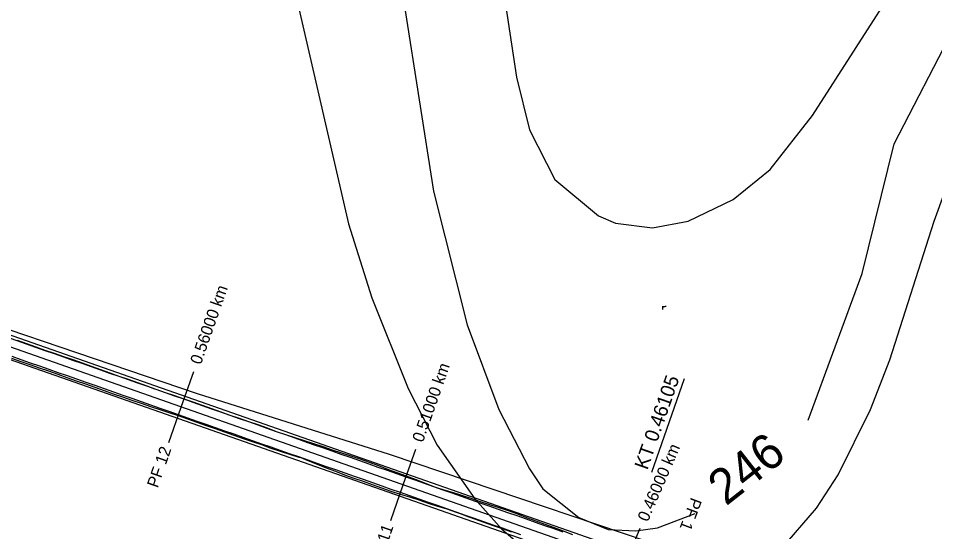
# Model space of a CAD drawing. Extents: x -555887 to -552101, y -1100251 to -1096546.
# Drawn here: x -553807.8 to -553613.1, y -1097242.2 to -1097133.2 of the extents above; entities that cross this region are included whole.
import ezdxf

# ---------------------------------------------------------------- set-up
doc = ezdxf.new("R2010")
doc.units = 0
for name, color, linetype in [('PARCELY_cesty', 7, 'Continuous'), ('POLYGONY_SITUACE_PF', 7, 'Continuous'), ('POLYGONY_SITUACE_PF_POPISY', 7, 'Continuous'), ('POLYGONY_SITUACE_PO', 7, 'Continuous'), ('vrstevnice', 7, 'Continuous'), ('ZSST', 7, 'Continuous')]:
    doc.layers.add(name, color=color, linetype=linetype)

msp = doc.modelspace()

# ---------------------------------------------------------------- linework, layer by layer
msp.add_line((-553673.2, -1097229.57), (-553666.23, -1097209.67))
at = {"layer": 'PARCELY_cesty'}
for points in [[(-553929.46, -1097158.38), (-553673.4, -1097248.15), (-553668.21, -1097254.17), (-553665.73, -1097263.94)], [(-553931.98, -1097162.8), (-553680.76, -1097250.77), (-553678.23, -1097251.97), (-553676.12, -1097253.6), (-553674.4, -1097255.65), (-553673.16, -1097258.01), (-553672.44, -1097260.58), (-553672.29, -1097263.25), (-553672.86, -1097266.82)]]:
    msp.add_lwpolyline(points, dxfattribs=at)
at = {"layer": 'POLYGONY_SITUACE_PF'}
for p, q in [((-553773.19, -1097215.75), (-553770.55, -1097208.2)), ((-553775.84, -1097223.3), (-553773.19, -1097215.75)), ((-553726, -1097232.27), (-553723.36, -1097224.72)), ((-553728.65, -1097239.82), (-553726, -1097232.27)), ((-553678.82, -1097248.83), (-553675.66, -1097241.49))]:
    msp.add_line(p, q, dxfattribs=at)
at = {"layer": 'POLYGONY_SITUACE_PO'}
for p, q in [((-553679.81, -1097248.45), (-553930.54, -1097160.65)), ((-553804.07, -1097203.08), (-553928.82, -1097159.4)), ((-553806.04, -1097202.39), (-553808.01, -1097201.7)), ((-553806.01, -1097202.3), (-553807.97, -1097201.6)), ((-553804.07, -1097203.08), (-553806.04, -1097202.39)), ((-553804.05, -1097203), (-553806.01, -1097202.3)), ((-553802.11, -1097203.77), (-553804.07, -1097203.08)), ((-553802.11, -1097203.77), (-553804.07, -1097203.08)), ((-553802.08, -1097203.7), (-553804.05, -1097203)), ((-553800.14, -1097204.46), (-553802.11, -1097203.77)), ((-553800.14, -1097204.46), (-553802.11, -1097203.77)), ((-553800.12, -1097204.4), (-553802.08, -1097203.7)), ((-553809.29, -1097205.38), (-553807.32, -1097206.05)), ((-553807.2, -1097205.7), (-553809.16, -1097205.01)), ((-553807.2, -1097205.7), (-553809.16, -1097205.01)), ((-553807.32, -1097206.05), (-553805.35, -1097206.72)), ((-553805.23, -1097206.39), (-553807.2, -1097205.7)), ((-553805.23, -1097206.39), (-553807.2, -1097205.7)), ((-553798.18, -1097205.15), (-553800.14, -1097204.46)), ((-553798.18, -1097205.15), (-553800.14, -1097204.46)), ((-553798.14, -1097205.05), (-553800.12, -1097204.4)), ((-553796.21, -1097205.84), (-553798.18, -1097205.15)), ((-553796.21, -1097205.84), (-553798.18, -1097205.15)), ((-553796.17, -1097205.72), (-553798.14, -1097205.05)), ((-553794.24, -1097206.52), (-553796.21, -1097205.84)), ((-553794.24, -1097206.52), (-553796.21, -1097205.84)), ((-553794.21, -1097206.43), (-553796.17, -1097205.72)), ((-553805.35, -1097206.72), (-553803.38, -1097207.39)), ((-553803.27, -1097207.07), (-553805.23, -1097206.39)), ((-553803.27, -1097207.07), (-553805.23, -1097206.39)), ((-553803.38, -1097207.39), (-553801.41, -1097208.07)), ((-553801.3, -1097207.76), (-553803.27, -1097207.07)), ((-553801.3, -1097207.76), (-553803.27, -1097207.07)), ((-553799.33, -1097208.45), (-553801.3, -1097207.76)), ((-553799.33, -1097208.45), (-553801.3, -1097207.76)), ((-553792.28, -1097207.21), (-553794.24, -1097206.52)), ((-553792.28, -1097207.21), (-553794.24, -1097206.52)), ((-553792.25, -1097207.14), (-553794.21, -1097206.43)), ((-553790.31, -1097207.9), (-553792.28, -1097207.21)), ((-553790.31, -1097207.9), (-553792.28, -1097207.21)), ((-553790.3, -1097207.86), (-553792.25, -1097207.14)), ((-553788.34, -1097208.59), (-553790.31, -1097207.9)), ((-553788.34, -1097208.59), (-553790.31, -1097207.9)), ((-553788.33, -1097208.56), (-553790.3, -1097207.86)), ((-553801.41, -1097208.07), (-553799.45, -1097208.78)), ((-553799.45, -1097208.78), (-553797.49, -1097209.49)), ((-553797.37, -1097209.14), (-553799.33, -1097208.45)), ((-553797.37, -1097209.14), (-553799.33, -1097208.45)), ((-553797.49, -1097209.49), (-553795.51, -1097210.16)), ((-553795.4, -1097209.83), (-553797.37, -1097209.14)), ((-553795.4, -1097209.83), (-553797.37, -1097209.14)), ((-553793.43, -1097210.52), (-553795.4, -1097209.83)), ((-553793.43, -1097210.52), (-553795.4, -1097209.83)), ((-553786.38, -1097209.28), (-553788.34, -1097208.59)), ((-553786.38, -1097209.28), (-553788.34, -1097208.59)), ((-553786.37, -1097209.25), (-553788.33, -1097208.56)), ((-553784.41, -1097209.97), (-553786.38, -1097209.28)), ((-553784.41, -1097209.97), (-553786.38, -1097209.28)), ((-553784.4, -1097209.92), (-553786.37, -1097209.25)), ((-553782.45, -1097210.66), (-553784.41, -1097209.97)), ((-553782.45, -1097210.66), (-553784.41, -1097209.97)), ((-553782.43, -1097210.62), (-553784.4, -1097209.92)), ((-553795.51, -1097210.16), (-553793.55, -1097210.84)), ((-553793.55, -1097210.84), (-553791.57, -1097211.5)), ((-553791.47, -1097211.2), (-553793.43, -1097210.52)), ((-553791.47, -1097211.2), (-553793.43, -1097210.52)), ((-553791.57, -1097211.5), (-553789.61, -1097212.22)), ((-553789.5, -1097211.89), (-553791.47, -1097211.2)), ((-553789.5, -1097211.89), (-553791.47, -1097211.2)), ((-553787.53, -1097212.58), (-553789.5, -1097211.89)), ((-553787.53, -1097212.58), (-553789.5, -1097211.89)), ((-553780.48, -1097211.34), (-553782.45, -1097210.66)), ((-553780.48, -1097211.34), (-553782.45, -1097210.66)), ((-553780.47, -1097211.32), (-553782.43, -1097210.62)), ((-553778.51, -1097212.03), (-553780.48, -1097211.34)), ((-553778.51, -1097212.03), (-553780.48, -1097211.34)), ((-553778.84, -1097211.92), (-553780.47, -1097211.32)), ((-553789.61, -1097212.22), (-553787.65, -1097212.91)), ((-553787.65, -1097212.91), (-553785.68, -1097213.6)), ((-553785.57, -1097213.27), (-553787.53, -1097212.58)), ((-553785.57, -1097213.27), (-553787.53, -1097212.58)), ((-553785.68, -1097213.6), (-553783.71, -1097214.27)), ((-553783.6, -1097213.96), (-553785.57, -1097213.27)), ((-553783.6, -1097213.96), (-553785.57, -1097213.27)), ((-553778.51, -1097212.03), (-553778.84, -1097211.92)), ((-553776.55, -1097212.72), (-553778.51, -1097212.03)), ((-553776.54, -1097212.69), (-553778.51, -1097212.03)), ((-553776.55, -1097212.72), (-553778.51, -1097212.03)), ((-553774.58, -1097213.41), (-553776.55, -1097212.72)), ((-553774.58, -1097213.41), (-553776.55, -1097212.72)), ((-553774.56, -1097213.36), (-553776.54, -1097212.69)), ((-553772.61, -1097214.1), (-553774.58, -1097213.41)), ((-553772.61, -1097214.1), (-553774.58, -1097213.41)), ((-553772.6, -1097214.04), (-553774.56, -1097213.36)), ((-553783.71, -1097214.27), (-553781.73, -1097214.92)), ((-553781.64, -1097214.65), (-553783.6, -1097213.96)), ((-553781.64, -1097214.65), (-553783.6, -1097213.96)), ((-553781.73, -1097214.92), (-553779.76, -1097215.6)), ((-553779.67, -1097215.34), (-553781.64, -1097214.65)), ((-553779.67, -1097215.34), (-553781.64, -1097214.65)), ((-553779.76, -1097215.6), (-553777.78, -1097216.25)), ((-553777.7, -1097216.02), (-553779.67, -1097215.34)), ((-553777.7, -1097216.02), (-553779.67, -1097215.34)), ((-553770.65, -1097214.79), (-553772.61, -1097214.1)), ((-553770.65, -1097214.79), (-553772.61, -1097214.1)), ((-553770.63, -1097214.72), (-553772.6, -1097214.04)), ((-553768.68, -1097215.48), (-553770.65, -1097214.79)), ((-553768.68, -1097215.48), (-553770.65, -1097214.79)), ((-553768.66, -1097215.42), (-553770.63, -1097214.72)), ((-553766.72, -1097216.16), (-553768.68, -1097215.48)), ((-553766.72, -1097216.16), (-553768.68, -1097215.48)), ((-553766.7, -1097216.13), (-553768.66, -1097215.42)), ((-553777.78, -1097216.25), (-553775.8, -1097216.89)), ((-553775.74, -1097216.71), (-553777.7, -1097216.02)), ((-553775.74, -1097216.71), (-553777.7, -1097216.02)), ((-553775.8, -1097216.89), (-553773.82, -1097217.54)), ((-553773.77, -1097217.4), (-553775.74, -1097216.71)), ((-553773.77, -1097217.4), (-553775.74, -1097216.71)), ((-553773.82, -1097217.54), (-553771.85, -1097218.22)), ((-553771.8, -1097218.09), (-553773.77, -1097217.4)), ((-553771.8, -1097218.09), (-553773.77, -1097217.4)), ((-553764.75, -1097216.85), (-553766.72, -1097216.16)), ((-553764.75, -1097216.85), (-553766.72, -1097216.16)), ((-553764.74, -1097216.83), (-553766.7, -1097216.13)), ((-553762.78, -1097217.54), (-553764.75, -1097216.85)), ((-553762.78, -1097217.54), (-553764.75, -1097216.85)), ((-553762.78, -1097217.52), (-553764.74, -1097216.83)), ((-553760.81, -1097218.2), (-553762.78, -1097217.52)), ((-553760.82, -1097218.23), (-553762.78, -1097217.54)), ((-553760.82, -1097218.23), (-553762.78, -1097217.54)), ((-553771.85, -1097218.22), (-553769.89, -1097218.93)), ((-553769.84, -1097218.78), (-553771.8, -1097218.09)), ((-553769.84, -1097218.78), (-553771.8, -1097218.09)), ((-553769.89, -1097218.93), (-553767.93, -1097219.64)), ((-553767.87, -1097219.47), (-553769.84, -1097218.78)), ((-553767.87, -1097219.47), (-553769.84, -1097218.78)), ((-553767.93, -1097219.64), (-553765.96, -1097220.32)), ((-553765.91, -1097220.16), (-553767.87, -1097219.47)), ((-553765.91, -1097220.16), (-553767.87, -1097219.47)), ((-553758.85, -1097218.92), (-553760.82, -1097218.23)), ((-553758.85, -1097218.92), (-553760.82, -1097218.23)), ((-553758.83, -1097218.86), (-553760.81, -1097218.2)), ((-553756.88, -1097219.61), (-553758.85, -1097218.92)), ((-553756.88, -1097219.61), (-553758.85, -1097218.92)), ((-553756.86, -1097219.53), (-553758.83, -1097218.86)), ((-553754.92, -1097220.29), (-553756.88, -1097219.61)), ((-553754.92, -1097220.29), (-553756.88, -1097219.61)), ((-553754.9, -1097220.25), (-553756.86, -1097219.53)), ((-553765.96, -1097220.32), (-553764, -1097221.01)), ((-553763.94, -1097220.84), (-553765.91, -1097220.16)), ((-553763.94, -1097220.84), (-553765.91, -1097220.16)), ((-553764, -1097221.01), (-553762.04, -1097221.72)), ((-553761.97, -1097221.53), (-553763.94, -1097220.84)), ((-553761.97, -1097221.53), (-553763.94, -1097220.84)), ((-553760.01, -1097222.22), (-553761.97, -1097221.53)), ((-553760.01, -1097222.22), (-553761.97, -1097221.53)), ((-553752.95, -1097220.98), (-553754.92, -1097220.29)), ((-553752.95, -1097220.98), (-553754.92, -1097220.29)), ((-553752.95, -1097220.98), (-553754.9, -1097220.25)), ((-553750.99, -1097221.67), (-553752.95, -1097220.98)), ((-553750.98, -1097221.66), (-553752.95, -1097220.98)), ((-553752.95, -1097220.98), (-553752.95, -1097220.98)), ((-553752.95, -1097220.98), (-553752.95, -1097220.98)), ((-553750.99, -1097221.67), (-553752.95, -1097220.98)), ((-553762.04, -1097221.72), (-553760.07, -1097222.4)), ((-553760.07, -1097222.4), (-553758.09, -1097223.05)), ((-553758.04, -1097222.91), (-553760.01, -1097222.22)), ((-553758.04, -1097222.91), (-553760.01, -1097222.22)), ((-553758.09, -1097223.05), (-553756.11, -1097223.7)), ((-553756.07, -1097223.6), (-553758.04, -1097222.91)), ((-553756.07, -1097223.6), (-553758.04, -1097222.91)), ((-553754.11, -1097224.29), (-553756.07, -1097223.6)), ((-553754.11, -1097224.29), (-553756.07, -1097223.6)), ((-553749.02, -1097222.36), (-553750.99, -1097221.67)), ((-553749.02, -1097222.36), (-553750.99, -1097221.67)), ((-553748.99, -1097222.29), (-553750.98, -1097221.66)), ((-553747.05, -1097223.05), (-553749.02, -1097222.36)), ((-553747.05, -1097223.05), (-553749.02, -1097222.36)), ((-553747.01, -1097222.93), (-553748.99, -1097222.29)), ((-553745.09, -1097223.74), (-553747.05, -1097223.05)), ((-553745.09, -1097223.74), (-553747.05, -1097223.05)), ((-553745.03, -1097223.57), (-553747.01, -1097222.93)), ((-553743.05, -1097224.22), (-553745.03, -1097223.57)), ((-553756.11, -1097223.7), (-553754.17, -1097224.45)), ((-553754.17, -1097224.45), (-553752.2, -1097225.15)), ((-553752.14, -1097224.98), (-553754.11, -1097224.29)), ((-553752.14, -1097224.98), (-553754.11, -1097224.29)), ((-553752.2, -1097225.15), (-553750.21, -1097225.77)), ((-553750.18, -1097225.66), (-553752.14, -1097224.98)), ((-553750.18, -1097225.66), (-553752.14, -1097224.98)), ((-553743.12, -1097224.43), (-553745.09, -1097223.74)), ((-553743.12, -1097224.43), (-553745.09, -1097223.74)), ((-553741.15, -1097225.11), (-553743.12, -1097224.43)), ((-553741.15, -1097225.11), (-553743.12, -1097224.43)), ((-553741.07, -1097224.87), (-553743.05, -1097224.22)), ((-553739.19, -1097225.8), (-553741.15, -1097225.11)), ((-553739.19, -1097225.8), (-553741.15, -1097225.11)), ((-553739.09, -1097225.52), (-553741.07, -1097224.87)), ((-553737.11, -1097226.19), (-553739.09, -1097225.52)), ((-553750.21, -1097225.77), (-553748.22, -1097226.37)), ((-553748.21, -1097226.35), (-553750.18, -1097225.66)), ((-553748.21, -1097226.35), (-553750.18, -1097225.66)), ((-553748.22, -1097226.37), (-553747.8, -1097226.49)), ((-553746.24, -1097227.04), (-553748.21, -1097226.35)), ((-553746.24, -1097227.04), (-553748.21, -1097226.35)), ((-553747.8, -1097226.49), (-553746.26, -1097227.1)), ((-553746.26, -1097227.1), (-553744.33, -1097227.87)), ((-553744.28, -1097227.73), (-553746.24, -1097227.04)), ((-553744.28, -1097227.73), (-553746.24, -1097227.04)), ((-553737.22, -1097226.49), (-553739.19, -1097225.8)), ((-553737.22, -1097226.49), (-553739.19, -1097225.8)), ((-553735.26, -1097227.18), (-553737.22, -1097226.49)), ((-553735.26, -1097227.18), (-553737.22, -1097226.49)), ((-553735.14, -1097226.85), (-553737.11, -1097226.19)), ((-553733.29, -1097227.87), (-553735.26, -1097227.18)), ((-553733.29, -1097227.87), (-553735.26, -1097227.18)), ((-553733.18, -1097227.54), (-553735.14, -1097226.85)), ((-553744.33, -1097227.87), (-553742.39, -1097228.63)), ((-553742.31, -1097228.42), (-553744.28, -1097227.73)), ((-553742.31, -1097228.42), (-553744.28, -1097227.73)), ((-553742.39, -1097228.63), (-553740.44, -1097229.37)), ((-553740.34, -1097229.11), (-553742.31, -1097228.42)), ((-553740.34, -1097229.11), (-553742.31, -1097228.42)), ((-553740.44, -1097229.37), (-553738.49, -1097230.12)), ((-553738.38, -1097229.79), (-553740.34, -1097229.11)), ((-553738.38, -1097229.79), (-553740.34, -1097229.11)), ((-553731.32, -1097228.56), (-553733.29, -1097227.87)), ((-553731.32, -1097228.56), (-553733.29, -1097227.87)), ((-553731.22, -1097228.26), (-553733.18, -1097227.54)), ((-553729.36, -1097229.25), (-553731.32, -1097228.56)), ((-553729.36, -1097229.25), (-553731.32, -1097228.56)), ((-553729.26, -1097228.98), (-553731.22, -1097228.26)), ((-553727.39, -1097229.93), (-553729.36, -1097229.25)), ((-553727.39, -1097229.93), (-553729.36, -1097229.25)), ((-553727.31, -1097229.7), (-553729.26, -1097228.98)), ((-553738.49, -1097230.12), (-553736.53, -1097230.82)), ((-553736.41, -1097230.48), (-553738.38, -1097229.79)), ((-553736.41, -1097230.48), (-553738.38, -1097229.79)), ((-553736.53, -1097230.82), (-553734.57, -1097231.52)), ((-553734.45, -1097231.17), (-553736.41, -1097230.48)), ((-553734.45, -1097231.17), (-553736.41, -1097230.48)), ((-553732.48, -1097231.86), (-553734.45, -1097231.17)), ((-553732.48, -1097231.86), (-553734.45, -1097231.17)), ((-553725.42, -1097230.62), (-553727.39, -1097229.93)), ((-553725.42, -1097230.62), (-553727.39, -1097229.93)), ((-553725.35, -1097230.42), (-553727.31, -1097229.7)), ((-553723.46, -1097231.31), (-553725.42, -1097230.62)), ((-553723.46, -1097231.31), (-553725.42, -1097230.62)), ((-553723.4, -1097231.16), (-553725.35, -1097230.42)), ((-553721.49, -1097232), (-553723.46, -1097231.31)), ((-553721.49, -1097232), (-553723.46, -1097231.31)), ((-553721.46, -1097231.9), (-553723.4, -1097231.16)), ((-553734.57, -1097231.52), (-553732.6, -1097232.21)), ((-553732.6, -1097232.21), (-553730.64, -1097232.9)), ((-553730.51, -1097232.55), (-553732.48, -1097231.86)), ((-553730.51, -1097232.55), (-553732.48, -1097231.86)), ((-553730.64, -1097232.9), (-553728.67, -1097233.58)), ((-553728.55, -1097233.24), (-553730.51, -1097232.55)), ((-553728.55, -1097233.24), (-553730.51, -1097232.55)), ((-553726.58, -1097233.93), (-553728.55, -1097233.24)), ((-553726.58, -1097233.93), (-553728.55, -1097233.24)), ((-553719.52, -1097232.69), (-553721.49, -1097232)), ((-553719.52, -1097232.69), (-553721.49, -1097232)), ((-553719.51, -1097232.66), (-553721.46, -1097231.9)), ((-553717.56, -1097233.38), (-553719.52, -1097232.69)), ((-553717.56, -1097233.38), (-553719.52, -1097232.69)), ((-553718.91, -1097232.9), (-553719.51, -1097232.66)), ((-553717.54, -1097233.31), (-553718.91, -1097232.9)), ((-553715.54, -1097233.91), (-553717.54, -1097233.31)), ((-553728.67, -1097233.58), (-553726.69, -1097234.23)), ((-553726.69, -1097234.23), (-553724.69, -1097234.84)), ((-553724.61, -1097234.61), (-553726.58, -1097233.93)), ((-553724.61, -1097234.61), (-553726.58, -1097233.93)), ((-553724.69, -1097234.84), (-553722.71, -1097235.48)), ((-553722.65, -1097235.3), (-553724.61, -1097234.61)), ((-553722.65, -1097235.3), (-553724.61, -1097234.61)), ((-553715.59, -1097234.07), (-553717.56, -1097233.38)), ((-553715.59, -1097234.07), (-553717.56, -1097233.38)), ((-553713.63, -1097234.75), (-553715.59, -1097234.07)), ((-553713.63, -1097234.75), (-553715.59, -1097234.07)), ((-553713.55, -1097234.54), (-553715.54, -1097233.91)), ((-553711.66, -1097235.44), (-553713.63, -1097234.75)), ((-553711.66, -1097235.44), (-553713.63, -1097234.75)), ((-553711.57, -1097235.18), (-553713.55, -1097234.54)), ((-553709.59, -1097235.85), (-553711.57, -1097235.18)), ((-553722.71, -1097235.48), (-553720.74, -1097236.14)), ((-553720.68, -1097235.99), (-553722.65, -1097235.3)), ((-553720.68, -1097235.99), (-553722.65, -1097235.3)), ((-553720.74, -1097236.14), (-553718.75, -1097236.78)), ((-553718.72, -1097236.68), (-553720.68, -1097235.99)), ((-553718.72, -1097236.68), (-553720.68, -1097235.99)), ((-553718.75, -1097236.78), (-553716.76, -1097237.4)), ((-553716.75, -1097237.37), (-553718.72, -1097236.68)), ((-553716.75, -1097237.37), (-553718.72, -1097236.68)), ((-553709.69, -1097236.13), (-553711.66, -1097235.44)), ((-553709.69, -1097236.13), (-553711.66, -1097235.44)), ((-553707.73, -1097236.82), (-553709.69, -1097236.13)), ((-553707.73, -1097236.82), (-553709.69, -1097236.13)), ((-553707.62, -1097236.51), (-553709.59, -1097235.85)), ((-553705.76, -1097237.51), (-553707.73, -1097236.82)), ((-553705.76, -1097237.51), (-553707.73, -1097236.82)), ((-553705.63, -1097237.14), (-553707.62, -1097236.51)), ((-553703.66, -1097237.82), (-553705.63, -1097237.14)), ((-553716.76, -1097237.4), (-553714.79, -1097238.09)), ((-553714.78, -1097238.06), (-553716.75, -1097237.37)), ((-553714.78, -1097238.06), (-553716.75, -1097237.37)), ((-553714.79, -1097238.09), (-553713.72, -1097238.43)), ((-553712.82, -1097238.75), (-553714.78, -1097238.06)), ((-553712.82, -1097238.75), (-553714.78, -1097238.06)), ((-553713.72, -1097238.43), (-553712.83, -1097238.77)), ((-553712.83, -1097238.77), (-553710.86, -1097239.47)), ((-553710.85, -1097239.43), (-553712.82, -1097238.75)), ((-553710.85, -1097239.43), (-553712.82, -1097238.75)), ((-553703.79, -1097238.2), (-553705.76, -1097237.51)), ((-553703.79, -1097238.2), (-553705.76, -1097237.51)), ((-553701.83, -1097238.88), (-553703.79, -1097238.2)), ((-553701.83, -1097238.88), (-553703.79, -1097238.2)), ((-553701.7, -1097238.53), (-553703.66, -1097237.82)), ((-553699.86, -1097239.57), (-553701.83, -1097238.88)), ((-553699.86, -1097239.57), (-553701.83, -1097238.88)), ((-553699.75, -1097239.25), (-553701.7, -1097238.53)), ((-553710.86, -1097239.47), (-553708.91, -1097240.2)), ((-553708.88, -1097240.12), (-553710.85, -1097239.43)), ((-553708.88, -1097240.12), (-553710.85, -1097239.43)), ((-553708.91, -1097240.2), (-553706.94, -1097240.89)), ((-553706.92, -1097240.81), (-553708.88, -1097240.12)), ((-553706.92, -1097240.81), (-553708.88, -1097240.12)), ((-553706.94, -1097240.89), (-553704.98, -1097241.57)), ((-553704.95, -1097241.5), (-553706.92, -1097240.81)), ((-553704.95, -1097241.5), (-553706.92, -1097240.81)), ((-553697.9, -1097240.26), (-553699.86, -1097239.57)), ((-553697.9, -1097240.26), (-553699.86, -1097239.57)), ((-553697.8, -1097239.98), (-553699.75, -1097239.25)), ((-553695.93, -1097240.95), (-553697.9, -1097240.26)), ((-553695.93, -1097240.95), (-553697.9, -1097240.26)), ((-553695.84, -1097240.7), (-553697.8, -1097239.98)), ((-553693.96, -1097241.64), (-553695.93, -1097240.95)), ((-553693.96, -1097241.64), (-553695.93, -1097240.95)), ((-553693.89, -1097241.42), (-553695.84, -1097240.7)), ((-553704.98, -1097241.57), (-553703.01, -1097242.25)), ((-553702.99, -1097242.19), (-553704.95, -1097241.5)), ((-553702.99, -1097242.19), (-553704.95, -1097241.5)), ((-553701.02, -1097242.88), (-553702.99, -1097242.19)), ((-553701.02, -1097242.88), (-553702.99, -1097242.19)), ((-553692, -1097242.33), (-553693.96, -1097241.64)), ((-553692, -1097242.33), (-553693.96, -1097241.64)), ((-553691.93, -1097242.14), (-553693.89, -1097241.42)), ((-553689.98, -1097242.86), (-553691.93, -1097242.14))]:
    msp.add_line(p, q, dxfattribs=at)
at = {"layer": 'vrstevnice'}
for points in [[(-553639.97, -1097218.52), (-553628.51, -1097187.36), (-553621.66, -1097159.86), (-553609, -1097135.32), (-553596.91, -1097115.83), (-553561.93, -1097073.8), (-553549.75, -1097054.11), (-553538.05, -1097027.22), (-553522.03, -1097005.66), (-553512.66, -1096995.33), (-553496.65, -1096980.64), (-553483.88, -1096971.28), (-553471.27, -1096959.01), (-553459.63, -1096948.68), (-553449.88, -1096934.99), (-553443.99, -1096922.83), (-553431.41, -1096907.72), (-553397.8, -1096886.72), (-553391.12, -1096882.2), (-553375.79, -1096871.02), (-553361.64, -1096865.72)], [(-553818.61, -1096942.38), (-553810.33, -1096947.43), (-553793.07, -1096964.2), (-553781.34, -1096980.05), (-553774.04, -1096990.66), (-553760.33, -1097017.53), (-553744.85, -1097052.01), (-553735.96, -1097077.11), (-553728.73, -1097111.63), (-553719.58, -1097169.85), (-553712.46, -1097198.28), (-553705.72, -1097216.29), (-553699.19, -1097228.85), (-553696.33, -1097233.14), (-553688.68, -1097239.18), (-553682.48, -1097241.73), (-553676.59, -1097242.05), (-553671.97, -1097241.41), (-553664.01, -1097238.39)], [(-553705.33, -1097123.18), (-553701.96, -1097145.64), (-553699.16, -1097156.88), (-553693.82, -1097167.41), (-553684.55, -1097175.13), (-553680.9, -1097176.67), (-553673.04, -1097177.66), (-553665.46, -1097176.25), (-553655.91, -1097171.62), (-553648.04, -1097165.3), (-553639.06, -1097153.79), (-553620.52, -1097124.86)], [(-553748.86, -1097128.23), (-553737.63, -1097176.81), (-553732.71, -1097192.54), (-553724.99, -1097211.78), (-553718.81, -1097223.85), (-553710.81, -1097235.23), (-553705.05, -1097241.69), (-553699.44, -1097246.46), (-553688.2, -1097253.2), (-553675, -1097257.83), (-553667.14, -1097257.97), (-553657.31, -1097255.73), (-553653.38, -1097253.2), (-553645.8, -1097246.04), (-553638.21, -1097237.19), (-553633.58, -1097230.17), (-553626.7, -1097216.27), (-553622.63, -1097205.74), (-553613.22, -1097176.25), (-553605.92, -1097156.17), (-553597.78, -1097139.18), (-553591.04, -1097127.53)]]:
    msp.add_lwpolyline(points, dxfattribs=at)
at = {"layer": 'ZSST'}
for points in [[(-553600.1, -1097268.75), (-553657.15, -1097250.01), (-553728.97, -1097225.8), (-553769.71, -1097212.97), (-553838.99, -1097189.46), (-553892.69, -1097170.63), (-553926.55, -1097160.61)], [(-553670.82, -1097195.05), (-553670.82, -1097194.32)], [(-553670.82, -1097194.55), (-553670.72, -1097194.46), (-553670.62, -1097194.4), (-553670.46, -1097194.35), (-553670.31, -1097194.33), (-553670.15, -1097194.32)]]:
    msp.add_lwpolyline(points, dxfattribs=at)

# ---------------------------------------------------------------- texts
msp.add_text('KT 0.46105', height=3, rotation=70.7015).set_placement((-553674.14, -1097229.24))
at = {"layer": 'POLYGONY_SITUACE_PF_POPISY'}
for s, rotation, p in [('0.56000 km', 70.7015, (-553769.03, -1097206.88)), ('0.51000 km', 70.7015, (-553721.84, -1097223.4)), ('PF 12', 70.7015, (-553778.2, -1097233.07)), ('0.46000 km', 66.6752, (-553674.04, -1097240.27)), ('PF 1', 249.509, (-553664.84, -1097234.8)), ('PF 11', 70.7015, (-553731.01, -1097249.59))]:
    msp.add_text(s, height=2.5, rotation=rotation, dxfattribs=at).set_placement(p)
at = {"layer": 'vrstevnice'}
msp.add_text('246', height=7.5, rotation=38.159, dxfattribs=at).set_placement((-553657.44, -1097236.89))

doc.saveas('drawing.dxf')
